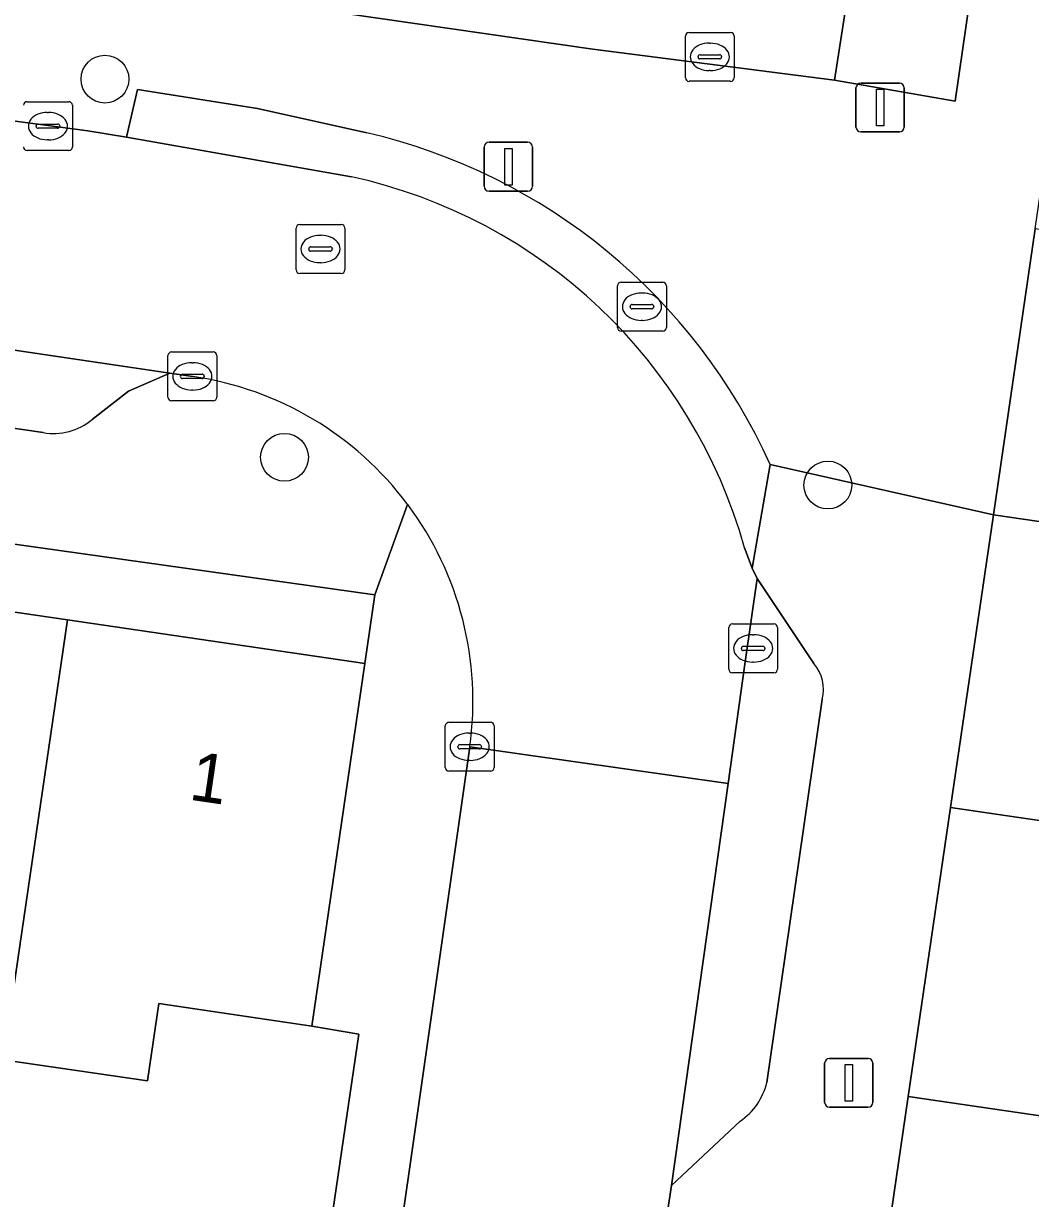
# Model space of a CAD drawing. Extents: x 163683 to 164494, y 382709 to 383872.
# Drawn here: x 164148.38 to 164168.99, y 383015.35 to 383039.39 of the extents above; entities that cross this region are included whole.
import ezdxf

# ---------------------------------------------------------------- set-up
doc = ezdxf.new("R2010")
doc.units = 0
for name, color, linetype in [('IMGEO_Boom', 7, 'Continuous'), ('IMGEO_Erf', 7, 'Continuous'), ('IMGEO_Groenvoorziening', 7, 'Continuous'), ('IMGEO_Kolk', 7, 'Continuous'), ('IMGEO_Lichtmast', 7, 'Continuous'), ('IMGEO_Muur', 7, 'Continuous'), ('IMGEO_Pand', 7, 'Continuous'), ('IMGEO_Pand_nummerreeks', 7, 'Continuous'), ('IMGEO_Parkeervlak_open', 7, 'Continuous'), ('IMGEO_Rijbaan_lokaal_open', 7, 'Continuous'), ('IMGEO_Rioolput', 7, 'Continuous'), ('IMGEO_Voetpad_open', 7, 'Continuous')]:
    doc.layers.add(name, color=color, linetype=linetype)

msp = doc.modelspace()

# ---------------------------------------------------------------- linework, layer by layer
at = {"layer": 'IMGEO_Boom'}
for centre in [(164150.045, 383038.256), (164153.721, 383030.518), (164164.844, 383029.95)]:
    msp.add_circle(centre, 0.489, dxfattribs=at)
at = {"layer": 'IMGEO_Erf'}
msp.add_lwpolyline([(164107.549, 383033.294), (164113.638, 383032.402), (164119.578, 383031.533), (164125.518, 383030.665), (164131.458, 383029.796), (164137.398, 383028.928), (164143.337, 383028.059), (164149.277, 383027.191), (164155.367, 383026.302), (164155.571, 383027.702), (164129.739, 383031.333), (164107.748, 383034.649)], close=True, dxfattribs=at)
msp.add_lwpolyline([(164153.476, 383006.694), (164155.244, 383018.714), (164154.282, 383018.881), (164151.146, 383019.34), (164150.915, 383017.757), (164147.961, 383018.188), (164145.968, 383018.478), (164144.983, 383018.622), (164145.206, 383020.147), (164142.243, 383020.58), (164139.307, 383021.009), (164139.125, 383019.759), (164136.122, 383020.198), (164133.074, 383020.643), (164133.262, 383021.929), (164130.37, 383022.352)], dxfattribs=at)
at = {"layer": 'IMGEO_Groenvoorziening'}
msp.add_lwpolyline([(164153.629, 383045.816), (164153.2, 383044.955), (164155.662, 383044.603), (164160.791, 383043.822), (164165.739, 383043.108), (164164.98, 383038.234), (164167.449, 383037.807), (164168.897, 383047.801), (164162.226, 383048.525)], dxfattribs=at)
at = {"layer": 'IMGEO_Kolk'}
for p, q in [((164161.927, 383038.285), (164161.927, 383039.137)), ((164162.002, 383039.211), (164162.854, 383039.211)), ((164162.928, 383039.137), (164162.928, 383038.285)), ((164162.415, 383038.991), (164162.44, 383038.991)), ((164162.186, 383038.705), (164162.186, 383038.717)), ((164162.624, 383038.668), (164162.226, 383038.668)), ((164162.229, 383038.754), (164162.627, 383038.754)), ((164162.67, 383038.717), (164162.67, 383038.705)), ((164162.438, 383038.431), (164162.413, 383038.431)), ((164162.854, 383038.211), (164162.002, 383038.211)), ((164148.452, 383037.794), (164149.304, 383037.794)), ((164149.378, 383037.72), (164149.378, 383036.868)), ((164148.865, 383037.574), (164148.89, 383037.574)), ((164148.636, 383037.288), (164148.636, 383037.3)), ((164149.074, 383037.251), (164148.676, 383037.251)), ((164148.679, 383037.337), (164149.077, 383037.337)), ((164149.12, 383037.3), (164149.12, 383037.288)), ((164148.888, 383037.014), (164148.863, 383037.014)), ((164149.304, 383036.794), (164148.452, 383036.794)), ((164151.409, 383032.674), (164152.261, 383032.674)), ((164151.334, 383031.748), (164151.334, 383032.6)), ((164151.822, 383032.454), (164151.847, 383032.454)), ((164152.335, 383032.6), (164152.335, 383031.748)), ((164151.593, 383032.168), (164151.593, 383032.18)), ((164151.636, 383032.217), (164152.034, 383032.217)), ((164152.077, 383032.18), (164152.077, 383032.168)), ((164152.031, 383032.131), (164151.633, 383032.131)), ((164151.845, 383031.894), (164151.82, 383031.894)), ((164152.261, 383031.674), (164151.409, 383031.674)), ((164162.889, 383027.108), (164163.741, 383027.108)), ((164162.814, 383026.182), (164162.814, 383027.034)), ((164163.302, 383026.888), (164163.327, 383026.888)), ((164163.815, 383027.034), (164163.815, 383026.182)), ((164163.073, 383026.602), (164163.073, 383026.614)), ((164163.116, 383026.651), (164163.514, 383026.651)), ((164163.557, 383026.614), (164163.557, 383026.602)), ((164163.511, 383026.565), (164163.113, 383026.565)), ((164163.325, 383026.328), (164163.3, 383026.328)), ((164163.741, 383026.108), (164162.889, 383026.108)), ((164157.011, 383024.17), (164157.011, 383025.022)), ((164157.086, 383025.096), (164157.938, 383025.096)), ((164158.012, 383025.022), (164158.012, 383024.17)), ((164157.499, 383024.876), (164157.524, 383024.876)), ((164157.27, 383024.59), (164157.27, 383024.602)), ((164157.708, 383024.553), (164157.31, 383024.553)), ((164157.313, 383024.639), (164157.711, 383024.639)), ((164157.754, 383024.602), (164157.754, 383024.59)), ((164157.522, 383024.316), (164157.497, 383024.316)), ((164157.938, 383024.096), (164157.086, 383024.096))]:
    msp.add_line(p, q, dxfattribs=at)
for points in [[(164161.927, 383038.285), (164161.927, 383039.137)], [(164162.002, 383039.211), (164162.854, 383039.211)], [(164162.928, 383039.137), (164162.928, 383038.285)], [(164162.854, 383038.211), (164162.002, 383038.211)], [(164148.452, 383037.794), (164149.304, 383037.794)], [(164149.378, 383037.72), (164149.378, 383036.868)], [(164149.304, 383036.794), (164148.452, 383036.794)], [(164151.409, 383032.674), (164152.261, 383032.674)], [(164151.334, 383031.748), (164151.334, 383032.6)], [(164152.335, 383032.6), (164152.335, 383031.748)], [(164152.261, 383031.674), (164151.409, 383031.674)], [(164162.889, 383027.108), (164163.741, 383027.108)], [(164162.814, 383026.182), (164162.814, 383027.034)], [(164163.815, 383027.034), (164163.815, 383026.182)], [(164163.741, 383026.108), (164162.889, 383026.108)], [(164157.011, 383024.17), (164157.011, 383025.022)], [(164157.086, 383025.096), (164157.938, 383025.096)], [(164158.012, 383025.022), (164158.012, 383024.17)], [(164157.938, 383024.096), (164157.086, 383024.096)]]:
    msp.add_lwpolyline(points, dxfattribs=at)
for centre, radius, start, end in [((164162.004, 383039.135), 0.0765, 91.552, 178.448), ((164162.004, 383039.135), 0.0765, 91.552, 178.448), ((164162.852, 383039.135), 0.0765, 1.552, 88.448), ((164162.852, 383039.135), 0.0765, 1.552, 88.448), ((164162.226, 383038.714), 0.0403, 85.8775, 175.7526), ((164162.223, 383038.704), 0.0366, 178.938, 274.7102), ((164162.627, 383038.711), 0.043, 264.8664, 352.4533), ((164162.631, 383038.716), 0.0386, 1.7309, 96.639), ((164162.004, 383038.287), 0.0765, 181.552, 268.448), ((164162.004, 383038.287), 0.0765, 181.552, 268.448), ((164162.852, 383038.287), 0.0765, 271.552, 358.448), ((164162.852, 383038.287), 0.0765, 271.552, 358.448), ((164148.454, 383037.718), 0.0765, 91.552, 178.448), ((164148.454, 383037.718), 0.0765, 91.552, 178.448), ((164149.302, 383037.718), 0.0765, 1.552, 88.448), ((164149.302, 383037.718), 0.0765, 1.552, 88.448), ((164148.676, 383037.297), 0.0403, 85.8775, 175.7526), ((164148.673, 383037.287), 0.0366, 178.938, 274.7102), ((164149.077, 383037.294), 0.043, 264.8664, 352.4533), ((164149.081, 383037.299), 0.0386, 1.7309, 96.639), ((164148.454, 383036.87), 0.0765, 181.552, 268.448), ((164148.454, 383036.87), 0.0765, 181.552, 268.448), ((164149.302, 383036.87), 0.0765, 271.552, 358.448), ((164149.302, 383036.87), 0.0765, 271.552, 358.448), ((164151.411, 383032.598), 0.0765, 91.552, 178.448), ((164151.411, 383032.598), 0.0765, 91.552, 178.448), ((164152.259, 383032.598), 0.0765, 1.552, 88.448), ((164152.259, 383032.598), 0.0765, 1.552, 88.448), ((164151.633, 383032.177), 0.0403, 85.8775, 175.7526), ((164151.63, 383032.167), 0.0366, 178.938, 274.7102), ((164152.034, 383032.174), 0.043, 264.8664, 352.4533), ((164152.038, 383032.179), 0.0386, 1.7309, 96.639), ((164151.411, 383031.75), 0.0765, 181.552, 268.448), ((164151.411, 383031.75), 0.0765, 181.552, 268.448), ((164152.259, 383031.75), 0.0765, 271.552, 358.448), ((164152.259, 383031.75), 0.0765, 271.552, 358.448), ((164162.891, 383027.032), 0.0765, 91.552, 178.448), ((164162.891, 383027.032), 0.0765, 91.552, 178.448), ((164163.739, 383027.032), 0.0765, 1.552, 88.448), ((164163.739, 383027.032), 0.0765, 1.552, 88.448), ((164163.113, 383026.611), 0.0403, 85.8775, 175.7526), ((164163.11, 383026.601), 0.0366, 178.938, 274.7102), ((164163.514, 383026.608), 0.043, 264.8664, 352.4533), ((164163.518, 383026.613), 0.0386, 1.7309, 96.639), ((164162.891, 383026.184), 0.0765, 181.552, 268.448), ((164162.891, 383026.184), 0.0765, 181.552, 268.448), ((164163.739, 383026.184), 0.0765, 271.552, 358.448), ((164163.739, 383026.184), 0.0765, 271.552, 358.448), ((164157.088, 383025.02), 0.0765, 91.552, 178.448), ((164157.088, 383025.02), 0.0765, 91.552, 178.448), ((164157.936, 383025.02), 0.0765, 1.552, 88.448), ((164157.936, 383025.02), 0.0765, 1.552, 88.448), ((164157.31, 383024.599), 0.0403, 85.8775, 175.7526), ((164157.307, 383024.589), 0.0366, 178.938, 274.7102), ((164157.711, 383024.596), 0.043, 264.8664, 352.4533), ((164157.715, 383024.601), 0.0386, 1.7309, 96.639), ((164157.088, 383024.172), 0.0765, 181.552, 268.448), ((164157.088, 383024.172), 0.0765, 181.552, 268.448), ((164157.936, 383024.172), 0.0765, 271.552, 358.448), ((164157.936, 383024.172), 0.0765, 271.552, 358.448)]:
    msp.add_arc(centre, radius, start, end, dxfattribs=at)
for centre, major_axis, ratio, start_param, end_param in [((164162.414, 383038.711), (-0.387, 0.002), 0.722429, 4.712389, 7.853982), ((164162.439, 383038.711), (-0.39, 0.002), 0.717154, 1.570796, 4.712389), ((164148.864, 383037.294), (-0.387, 0.002), 0.722429, 4.712389, 7.853982), ((164148.889, 383037.294), (-0.39, 0.002), 0.717154, 1.570796, 4.712389), ((164151.821, 383032.174), (-0.387, 0.002), 0.722429, 4.712389, 7.853982), ((164151.846, 383032.174), (-0.39, 0.002), 0.717154, 1.570796, 4.712389), ((164163.301, 383026.608), (-0.387, 0.002), 0.722429, 4.712389, 7.853982), ((164163.326, 383026.608), (-0.39, 0.002), 0.717154, 1.570796, 4.712389), ((164157.498, 383024.596), (-0.387, 0.002), 0.722429, 4.712389, 7.853982), ((164157.523, 383024.596), (-0.39, 0.002), 0.717154, 1.570796, 4.712389)]:
    msp.add_ellipse(centre, major_axis=major_axis, ratio=ratio, start_param=start_param, end_param=end_param, dxfattribs=at)
at = {"layer": 'IMGEO_Lichtmast'}
for p, q in [((164165.519, 383038.176), (164166.309, 383038.176)), ((164166.309, 383038.176), (164165.519, 383038.176)), ((164165.419, 383037.276), (164165.419, 383038.076)), ((164165.419, 383038.076), (164165.419, 383037.276)), ((164166.409, 383038.076), (164166.409, 383037.276)), ((164166.409, 383037.276), (164166.409, 383038.076)), ((164157.908, 383036.964), (164158.698, 383036.964)), ((164158.698, 383036.964), (164157.908, 383036.964)), ((164166.309, 383037.176), (164165.519, 383037.176)), ((164165.519, 383037.176), (164166.309, 383037.176)), ((164157.808, 383036.064), (164157.808, 383036.864)), ((164157.808, 383036.864), (164157.808, 383036.064)), ((164158.798, 383036.864), (164158.798, 383036.064)), ((164158.798, 383036.064), (164158.798, 383036.864)), ((164158.698, 383035.964), (164157.908, 383035.964)), ((164157.908, 383035.964), (164158.698, 383035.964)), ((164164.878, 383018.219), (164165.668, 383018.219)), ((164165.668, 383018.219), (164164.878, 383018.219)), ((164164.778, 383017.319), (164164.778, 383018.119)), ((164164.778, 383018.119), (164164.778, 383017.319)), ((164165.768, 383018.119), (164165.768, 383017.319)), ((164165.768, 383017.319), (164165.768, 383018.119)), ((164165.668, 383017.219), (164164.878, 383017.219)), ((164164.878, 383017.219), (164165.668, 383017.219))]:
    msp.add_line(p, q, dxfattribs=at)
for points in [[(164165.839, 383038.051), (164165.989, 383038.051), (164165.989, 383037.301), (164165.839, 383037.301), (164165.839, 383038.051)], [(164158.228, 383036.839), (164158.378, 383036.839), (164158.378, 383036.089), (164158.228, 383036.089), (164158.228, 383036.839)], [(164165.198, 383018.094), (164165.348, 383018.094), (164165.348, 383017.344), (164165.198, 383017.344), (164165.198, 383018.094)]]:
    msp.add_lwpolyline(points, dxfattribs=at)
for centre, start, end in [((164165.519, 383038.076), 90, 180), ((164165.519, 383038.076), 90, 180), ((164166.309, 383038.076), 0, 90), ((164166.309, 383038.076), 360, 90), ((164165.519, 383037.276), 180, 270), ((164165.519, 383037.276), 180, 270), ((164166.309, 383037.276), 270, 0), ((164166.309, 383037.276), 270, 0), ((164157.908, 383036.864), 90, 180), ((164157.908, 383036.864), 90, 180), ((164158.698, 383036.864), 0, 90), ((164158.698, 383036.864), 360, 90), ((164157.908, 383036.064), 180, 270), ((164157.908, 383036.064), 180, 270), ((164158.698, 383036.064), 270, 0), ((164158.698, 383036.064), 270, 0), ((164164.878, 383018.119), 90, 180), ((164164.878, 383018.119), 90, 180), ((164165.668, 383018.119), 0, 90), ((164165.668, 383018.119), 360, 90), ((164164.878, 383017.319), 180, 270), ((164164.878, 383017.319), 180, 270), ((164165.668, 383017.319), 270, 0), ((164165.668, 383017.319), 270, 0)]:
    msp.add_arc(centre, 0.1, start, end, dxfattribs=at)
at = {"layer": 'IMGEO_Muur'}
msp.add_lwpolyline([(164154.282, 383018.881), (164155.244, 383018.714), (164153.476, 383006.694)], dxfattribs=at)
at = {"layer": 'IMGEO_Pand'}
for points in [[(164179.906, 383033.61), (164176.354, 383034.129), (164169.088, 383035.191), (164168.232, 383029.342), (164176.74, 383028.098), (164179.05, 383027.76)], [(164174.629, 383022.291), (164175.072, 383025.316), (164176.307, 383025.136), (164176.74, 383028.098), (164168.232, 383029.342), (164167.356, 383023.354)], [(164149.277, 383027.191), (164143.337, 383028.059), (164142.243, 383020.58), (164145.206, 383020.147), (164144.983, 383018.622), (164145.968, 383018.478), (164147.961, 383018.188)], [(164149.277, 383027.191), (164147.961, 383018.188), (164150.915, 383017.757), (164151.146, 383019.34), (164154.282, 383018.881), (164155.367, 383026.302)], [(164166.491, 383017.442), (164175.49, 383016.126), (164175.788, 383018.168), (164175.935, 383019.174), (164174.21, 383019.427), (164174.629, 383022.291), (164167.356, 383023.354)], [(164166.491, 383017.442), (164165.607, 383011.403), (164173.025, 383010.318), (164173.483, 383013.451), (164175.067, 383013.22), (164175.49, 383016.126)]]:
    msp.add_lwpolyline(points, close=True, dxfattribs=at)
at = {"layer": 'IMGEO_Parkeervlak_open'}
msp.add_lwpolyline([(164165.739, 383043.108), (164160.791, 383043.822), (164155.662, 383044.603), (164153.2, 383044.955), (164152.624, 383041.139), (164152.452, 383039.999), (164154.923, 383039.607), (164160.032, 383038.872), (164164.98, 383038.234)], close=True, dxfattribs=at)
for points in [[(164149.783, 383031.293), (164150.53, 383031.869), (164151.376, 383032.242), (164134.603, 383034.719), (164134.074, 383034.797), (164134.811, 383034.393), (164135.719, 383033.24), (164136.572, 383032.798), (164148.781, 383031.023)], [(164164.556, 383026.298), (164163.395, 383028.038), (164163.154, 383026.331), (164162.802, 383023.844), (164161.64, 383015.622), (164163.047, 383016.934)], [(164163.593, 383017.725), (164163.977, 383020.366), (164164.729, 383025.565)]]:
    msp.add_lwpolyline(points, dxfattribs=at)
for centre, radius, start, end in [((164148.99, 383032.243), 1.238, 260.2943, 309.8673), ((164163.946, 383025.767), 0.809, 345.5293, 41.0302), ((164162.313, 383018.025), 1.315, 303.9439, 346.8241)]:
    msp.add_arc(centre, radius, start, end, dxfattribs=at)
at = {"layer": 'IMGEO_Rijbaan_lokaal_open'}
for points in [[(164155.09, 383036.258), (164150.489, 383037.071), (164149.698, 383037.199), (164148.16, 383037.399), (164135.307, 383039.353), (164134.603, 383034.719), (164151.376, 383032.242), (164151.842, 383032.173)], [(164157.512, 383024.592), (164162.802, 383023.844), (164163.154, 383026.331), (164163.395, 383028.038), (164163.295, 383028.249), (164163.138, 383028.667)], [(164161.486, 383014.587), (164161.64, 383015.622), (164162.802, 383023.844), (164157.512, 383024.592), (164154.966, 383006.746), (164154.423, 383002.944), (164154.003, 383000), (164153.797, 382998.804), (164148.89, 382965.262), (164148.828, 382964.839), (164153.673, 382964.128), (164153.712, 382964.394), (164158.474, 382996.758), (164158.492, 382997.006), (164158.548, 382997.381)]]:
    msp.add_lwpolyline(points, dxfattribs=at)
for centre, radius, start, end in [((164152.794, 383025.762), 10.745, 15.6879, 77.6597), ((164150.868, 383025.533), 6.711, 36.8003, 81.656), ((164150.869, 383025.534), 6.71, 351.9263, 36.792)]:
    msp.add_arc(centre, radius, start, end, dxfattribs=at)
at = {"layer": 'IMGEO_Rioolput'}
for p, q in [((164154.032, 383035.28), (164154.884, 383035.28)), ((164153.957, 383034.354), (164153.957, 383035.206)), ((164154.445, 383035.06), (164154.47, 383035.06)), ((164154.958, 383035.206), (164154.958, 383034.354)), ((164154.216, 383034.774), (164154.216, 383034.786)), ((164154.259, 383034.823), (164154.657, 383034.823)), ((164154.7, 383034.786), (164154.7, 383034.774)), ((164154.654, 383034.737), (164154.256, 383034.737)), ((164154.468, 383034.5), (164154.443, 383034.5)), ((164154.884, 383034.28), (164154.032, 383034.28)), ((164160.612, 383034.1), (164161.464, 383034.1)), ((164160.537, 383033.174), (164160.537, 383034.026)), ((164161.025, 383033.88), (164161.05, 383033.88)), ((164161.538, 383034.026), (164161.538, 383033.174)), ((164160.796, 383033.594), (164160.796, 383033.606)), ((164160.839, 383033.643), (164161.237, 383033.643)), ((164161.28, 383033.606), (164161.28, 383033.594)), ((164161.234, 383033.557), (164160.836, 383033.557)), ((164161.464, 383033.1), (164160.612, 383033.1)), ((164161.048, 383033.32), (164161.023, 383033.32))]:
    msp.add_line(p, q, dxfattribs=at)
for points in [[(164154.032, 383035.28), (164154.884, 383035.28)], [(164153.957, 383034.354), (164153.957, 383035.206)], [(164154.958, 383035.206), (164154.958, 383034.354)], [(164154.884, 383034.28), (164154.032, 383034.28)], [(164160.612, 383034.1), (164161.464, 383034.1)], [(164160.537, 383033.174), (164160.537, 383034.026)], [(164161.538, 383034.026), (164161.538, 383033.174)], [(164161.464, 383033.1), (164160.612, 383033.1)]]:
    msp.add_lwpolyline(points, dxfattribs=at)
for centre, radius, start, end in [((164154.034, 383035.204), 0.0765, 91.552, 178.448), ((164154.034, 383035.204), 0.0765, 91.552, 178.448), ((164154.882, 383035.204), 0.0765, 1.552, 88.448), ((164154.882, 383035.204), 0.0765, 1.552, 88.448), ((164154.256, 383034.783), 0.0403, 85.8775, 175.7526), ((164154.661, 383034.785), 0.0386, 1.7309, 96.639), ((164154.253, 383034.773), 0.0366, 178.938, 274.7102), ((164154.657, 383034.78), 0.043, 264.8664, 352.4533), ((164154.034, 383034.356), 0.0765, 181.552, 268.448), ((164154.034, 383034.356), 0.0765, 181.552, 268.448), ((164154.882, 383034.356), 0.0765, 271.552, 358.448), ((164154.882, 383034.356), 0.0765, 271.552, 358.448), ((164160.614, 383034.024), 0.0765, 91.552, 178.448), ((164160.614, 383034.024), 0.0765, 91.552, 178.448), ((164161.462, 383034.024), 0.0765, 1.552, 88.448), ((164161.462, 383034.024), 0.0765, 1.552, 88.448), ((164160.836, 383033.603), 0.0403, 85.8775, 175.7526), ((164160.833, 383033.593), 0.0366, 178.938, 274.7102), ((164161.237, 383033.6), 0.043, 264.8664, 352.4533), ((164161.241, 383033.605), 0.0386, 1.7309, 96.639), ((164160.614, 383033.176), 0.0765, 181.552, 268.448), ((164160.614, 383033.176), 0.0765, 181.552, 268.448), ((164161.462, 383033.176), 0.0765, 271.552, 358.448), ((164161.462, 383033.176), 0.0765, 271.552, 358.448)]:
    msp.add_arc(centre, radius, start, end, dxfattribs=at)
for centre, major_axis, ratio, start_param, end_param in [((164154.444, 383034.78), (-0.387, 0.002), 0.722429, 4.712389, 7.853982), ((164154.469, 383034.78), (-0.39, 0.002), 0.717154, 1.570796, 4.712389), ((164161.024, 383033.6), (-0.387, 0.002), 0.722429, 4.712389, 7.853982), ((164161.049, 383033.6), (-0.39, 0.002), 0.717154, 1.570796, 4.712389)]:
    msp.add_ellipse(centre, major_axis=major_axis, ratio=ratio, start_param=start_param, end_param=end_param, dxfattribs=at)
at = {"layer": 'IMGEO_Voetpad_open'}
for points in [[(164163.661, 383030.372), (164168.232, 383029.342), (164169.088, 383035.191), (164169.96, 383041.146), (164170.868, 383047.353), (164168.897, 383047.801), (164167.449, 383037.807), (164164.98, 383038.234), (164160.032, 383038.872), (164154.923, 383039.607), (164152.452, 383039.999), (164152.624, 383041.139), (164150.932, 383041.393), (164143.649, 383042.486)], [(164137.638, 383040.839), (164145.976, 383039.564), (164146.622, 383039.274), (164147.229, 383038.285), (164148.16, 383037.399), (164149.698, 383037.199), (164150.489, 383037.071), (164150.71, 383038.043), (164153.167, 383037.656), (164155.404, 383037.158)], [(164155.404, 383037.158), (164153.167, 383037.656), (164150.71, 383038.043), (164150.489, 383037.071), (164155.09, 383036.258)], [(164105.508, 383034.961), (164107.748, 383034.649), (164129.739, 383031.333), (164155.571, 383027.702), (164156.242, 383029.553)], [(164148.781, 383031.023), (164136.572, 383032.798)], [(164151.842, 383032.173), (164151.376, 383032.242), (164150.53, 383031.869), (164149.783, 383031.293)], [(164163.138, 383028.667), (164163.295, 383028.249), (164163.661, 383030.372)], [(164166.491, 383017.442), (164167.356, 383023.354), (164168.232, 383029.342), (164163.661, 383030.372), (164163.295, 383028.249), (164163.395, 383028.038), (164164.556, 383026.298)], [(164156.242, 383029.553), (164155.571, 383027.702), (164155.367, 383026.302), (164154.282, 383018.881), (164155.244, 383018.714), (164153.476, 383006.694), (164152.925, 383002.989), (164151.45, 383003.208), (164151.417, 383002.982), (164151.195, 383001.469), (164150.98, 383000), (164145.92, 382965.49), (164145.469, 382962.412), (164140.229, 382926.679), (164139.939, 382924.7), (164139.409, 382922.626), (164138.954, 382920.045), (164138.554, 382917.653), (164137.738, 382912.877), (164140.818, 382912.448), (164141.032, 382913.929), (164141.145, 382914.701)], [(164164.729, 383025.565), (164163.977, 383020.366), (164163.593, 383017.725)], [(164154.423, 383002.944), (164153.937, 383003.015), (164154.483, 383006.816), (164154.966, 383006.746), (164157.512, 383024.592)], [(164164.39, 383008.516), (164165.607, 383011.403), (164166.491, 383017.442)], [(164163.047, 383016.934), (164161.64, 383015.622), (164161.486, 383014.587)]]:
    msp.add_lwpolyline(points, dxfattribs=at)
for centre, radius, start, end in [((164152.677, 383025.424), 12.047, 24.2516, 76.9184), ((164152.677, 383025.424), 12.047, 24.2516, 76.9184), ((164152.794, 383025.762), 10.745, 15.6879, 77.6597), ((164150.868, 383025.533), 6.711, 36.8003, 81.656), ((164148.99, 383032.243), 1.238, 260.2943, 309.8673), ((164150.869, 383025.534), 6.71, 351.9263, 36.792), ((164163.946, 383025.767), 0.809, 345.5293, 41.0302), ((164162.313, 383018.025), 1.315, 303.9439, 346.8241)]:
    msp.add_arc(centre, radius, start, end, dxfattribs=at)

# ---------------------------------------------------------------- texts
at = {"layer": 'IMGEO_Pand_nummerreeks'}
msp.add_text('1', height=1, rotation=351.6811, dxfattribs=at).set_placement((164151.744, 383023.517))

doc.saveas('drawing.dxf')
